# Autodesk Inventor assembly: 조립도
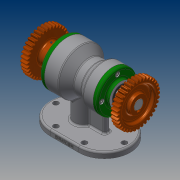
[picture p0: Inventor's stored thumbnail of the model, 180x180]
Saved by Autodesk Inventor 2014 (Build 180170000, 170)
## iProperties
Created: 2020-01
Part Number: 조립도
Document SubType Name: Assembly
Designer: kh
Author: kh
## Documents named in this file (13)
- C:\Users\kh\Desktop\700104V1037\조립도.iam
- C:\Users\kh\Desktop\700104V1037\본체.ipt
- C:\Users\kh\Desktop\700104V1037\축.ipt
- C:\Users\kh\Desktop\700104V1037\베어링 6205.ipt
- C:\Users\kh\Desktop\700104V1037\뒤커버.ipt
- C:\Users\kh\Desktop\700104V1037\앞커버.ipt
- C:\Users\kh\Desktop\700104V1037\베어링 6203.ipt
- C:\Users\kh\Desktop\700104V1037\Ű 5 x 5 x 18.ipt
- C:\Users\kh\Desktop\700104V1037\볼트 M4.ipt
- C:\Users\kh\Desktop\700104V1037\오일 실 25 38 8.ipt
- C:\Users\kh\Desktop\700104V1037\오일 실 17 30 8.ipt
- C:\Users\kh\Desktop\700104V1037\스퍼기어.ipt
- C:\Users\kh\Desktop\700104V1037\멈춤나사 M3.ipt
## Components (2 placed, 1 different names)
1. Ű 5 x 5 x 18:1 — Mate:12, Mate:13, Mate:14, Mate:30, Mate:32
2. Ű 5 x 5 x 18:2 — Mate:16, Mate:17, Mate:18, Mate:29, Mate:34
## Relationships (10: Mate 10)
- Mate:12: Ű 5 x 5 x 18:1
- Mate:13: Ű 5 x 5 x 18:1
- Mate:14: Ű 5 x 5 x 18:1
- Mate:16: Ű 5 x 5 x 18:2
- Mate:17: Ű 5 x 5 x 18:2
- Mate:18: Ű 5 x 5 x 18:2
- Mate:29: Ű 5 x 5 x 18:2
- Mate:30: Ű 5 x 5 x 18:1
- Mate:32: Ű 5 x 5 x 18:1
- Mate:34: Ű 5 x 5 x 18:2
